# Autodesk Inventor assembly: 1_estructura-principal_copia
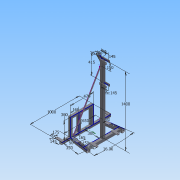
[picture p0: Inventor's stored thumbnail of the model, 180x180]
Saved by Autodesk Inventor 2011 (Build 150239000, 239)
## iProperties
Created: 2020-11
Part Number: 1_estructura-principal_copia
Document SubType Name: Assembly
Designer: PC
Mass: 39331.2 g
Surface Area: 23911.8 cm^2
Volume: 5003.97 cm^3
Density: 7.86 g/cm^3
_SolveAssemblyDoc: Frame Generator Solve Assembly
_Version: 15.0.0
Author: PC
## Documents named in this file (3)
- C:\Users\PC\Documents\Inventor\workshop-crane-powered-by-drill\1_estructura-principal.iam
- C:\Users\PC\Documents\Inventor\workshop-crane-powered-by-drill\1_marco-inferior\Frame\Frame0001.iam
- C:\Users\PC\Documents\Inventor\workshop-crane-powered-by-drill\1_estructura-principal_esqueleto.ipt
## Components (2 placed, 2 different names)
1. 1_estructura-principal_esqueleto:1
2. Frame0001:1 [sub-assembly]
